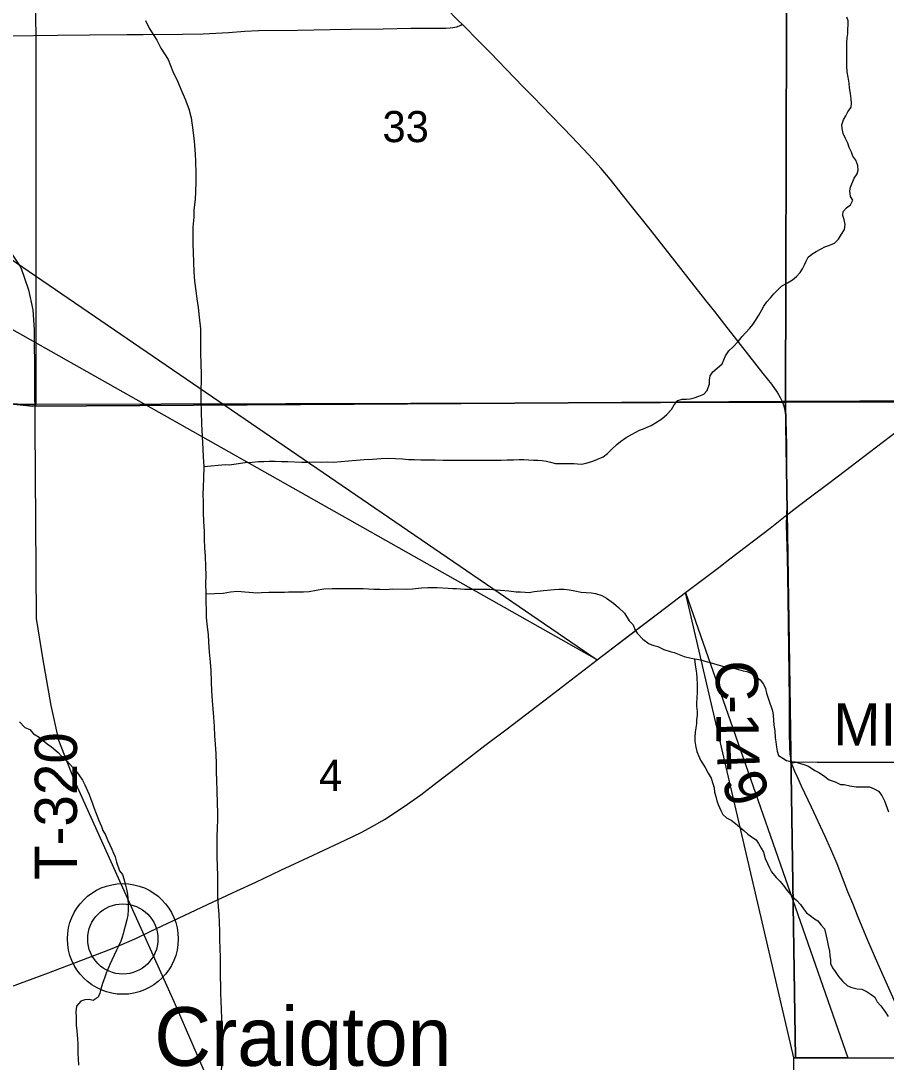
# Model space of a CAD drawing. Extents: x 0 to 34, y 0 to 22.
# Drawn here: x 5.452 to 6.615, y 17.529 to 18.929 of the extents above; entities that cross this region are included whole.
import ezdxf

# ---------------------------------------------------------------- set-up
doc = ezdxf.new("R2010")
doc.units = 0
for name, color, linetype in [('Default', 7, 'Continuous'), ('GM_X_County_Road', 7, 'Continuous'), ('GM_X_County_Road_Text', 7, 'Continuous'), ('GM_X_Minor_River', 7, 'Continuous'), ('GM_X_Rail_Line', 7, 'Continuous'), ('GM_X_Section', 7, 'Continuous'), ('GM_X_Section_Text', 7, 'Continuous'), ('GM_X_State_Route', 7, 'Continuous'), ('GM_X_Township_Road', 7, 'Continuous'), ('GM_X_Township_Road_Text', 7, 'Continuous'), ('GM_X_Unincorporated', 7, 'Continuous'), ('GM_X_Unincorporated_Location', 7, 'Continuous'), ('GM_X_Unincorporated_Text', 7, 'Continuous'), ('SH_Text', 7, 'Continuous')]:
    doc.layers.add(name, color=color, linetype=linetype)

msp = doc.modelspace()

# ---------------------------------------------------------------- linework, layer by layer
at = {"layer": 'Default'}
for points in [[(5.3223, 18.688), (6.2262, 18.0698), (5.3223, 18.5805)], [(6.4908, 17.5349), (6.3453, 18.1606), (6.5634, 17.5349)]]:
    msp.add_lwpolyline(points, close=True, dxfattribs=at)
for points in [[(6.6827, 18.4182), (6.4755, 18.4174), (5.4679, 18.4109), (5.4247, 18.4153)], [(5.4247, 18.4153), (5.4679, 18.4109), (6.4755, 18.4174), (6.6827, 18.4182)]]:
    msp.add_lwpolyline(points, dxfattribs=at)
at = {"layer": 'GM_X_County_Road'}
for points in [[(6.0449, 18.9245), (6.0402, 18.9292), (6.0056, 18.9649), (5.976, 18.9964)], [(6.4757, 18.4168), (6.473, 18.4223), (6.4682, 18.4302), (6.4612, 18.4404), (6.4497, 18.4551), (6.4189, 18.494), (6.3979, 18.5209), (6.3844, 18.5381), (6.3749, 18.5503), (6.3614, 18.5673), (6.3306, 18.6063), (6.2982, 18.6481), (6.2691, 18.6845), (6.2439, 18.716), (6.232, 18.7303), (6.2154, 18.7488), (6.1919, 18.7736), (6.1811, 18.7847), (6.1638, 18.8026), (6.1531, 18.8138), (6.14, 18.8271), (6.1269, 18.8403), (6.0928, 18.8755), (6.0838, 18.8849), (6.0686, 18.9005), (6.0449, 18.9245)], [(6.4811, 18.2648), (6.4816, 18.2769), (6.4816, 18.2879), (6.4814, 18.3003), (6.4813, 18.3314), (6.4811, 18.3562), (6.4807, 18.3774), (6.4805, 18.3899), (6.4801, 18.3991), (6.4792, 18.4051), (6.4778, 18.4111), (6.4757, 18.4168)], [(6.4879, 17.9317), (6.4874, 17.9337), (6.4865, 17.9376), (6.4858, 17.9431), (6.4853, 17.9528), (6.4849, 17.9715), (6.4847, 18.015), (6.4844, 18.0523), (6.4838, 18.0834), (6.4834, 18.1207), (6.4825, 18.1829), (6.4821, 18.2078), (6.4807, 18.2517), (6.4811, 18.2648)], [(6.4879, 17.9317), (6.4945, 17.9326), (6.5036, 17.9327), (6.5222, 17.9326), (6.544, 17.9325), (6.6029, 17.9324), (6.6277, 17.9324)], [(6.6597, 17.5349), (6.6531, 17.5517), (6.6469, 17.5659), (6.6353, 17.591), (6.6286, 17.6054), (6.6203, 17.6244), (6.6037, 17.6616), (6.5904, 17.6928), (6.5774, 17.7243), (6.5699, 17.7425), (6.5635, 17.7581), (6.5488, 17.7957), (6.5406, 17.8156), (6.533, 17.8326), (6.5144, 17.872), (6.5011, 17.9), (6.4959, 17.9113), (6.4922, 17.9198), (6.4891, 17.9279), (6.4879, 17.9317)]]:
    msp.add_lwpolyline(points, dxfattribs=at)
at = {"layer": 'GM_X_Minor_River'}
for points in [[(5.6195, 18.9296), (5.6245, 18.919), (5.6344, 18.9031), (5.6401, 18.8921), (5.6497, 18.877), (5.6562, 18.861), (5.6623, 18.8478), (5.6684, 18.8341), (5.6726, 18.8239), (5.6776, 18.8106), (5.6806, 18.7985), (5.683, 18.7822), (5.6846, 18.767)], [(6.4503, 18.5452), (6.4545, 18.5513), (6.4594, 18.5566), (6.464, 18.5619), (6.469, 18.5676), (6.4743, 18.5722), (6.4823, 18.5767), (6.4888, 18.5809), (6.4945, 18.5855), (6.4994, 18.5908), (6.5025, 18.5957), (6.5051, 18.6011), (6.5074, 18.606), (6.5101, 18.6113), (6.515, 18.6151), (6.5207, 18.6189), (6.5276, 18.6227), (6.5326, 18.6254), (6.5379, 18.6269), (6.5455, 18.6303), (6.5508, 18.6353), (6.555, 18.6421), (6.5588, 18.6486), (6.5596, 18.655), (6.5584, 18.6619), (6.5565, 18.6672), (6.5569, 18.6725), (6.5614, 18.6778), (6.5668, 18.6816), (6.5702, 18.6877), (6.5671, 18.6927), (6.566, 18.7003), (6.5671, 18.7056), (6.5716, 18.7174), (6.5758, 18.7231), (6.577, 18.7284), (6.5766, 18.7345), (6.5739, 18.7417), (6.57, 18.747), (6.5681, 18.7524), (6.5651, 18.7588), (6.5631, 18.7645), (6.5601, 18.771), (6.557, 18.7775), (6.5555, 18.7843), (6.5554, 18.7893), (6.5573, 18.7957), (6.5604, 18.8014), (6.5634, 18.8068), (6.5676, 18.8128), (6.5683, 18.8182), (6.568, 18.8242), (6.5668, 18.8315), (6.5656, 18.8391), (6.5652, 18.8452), (6.5637, 18.8531), (6.5625, 18.8604), (6.5621, 18.868), (6.5621, 18.8995), (6.5624, 18.906), (6.5632, 18.9117), (6.5635, 18.9174), (6.5639, 18.9239), (6.5639, 18.9288), (6.562, 18.9341)], [(5.6846, 18.767), (5.6861, 18.7499), (5.6866, 18.7401), (5.687, 18.7237), (5.687, 18.7131), (5.6867, 18.6991), (5.686, 18.6888), (5.6845, 18.6751), (5.6842, 18.6649), (5.6831, 18.6516), (5.6831, 18.6414), (5.6828, 18.6288), (5.6832, 18.6175), (5.6837, 18.6046), (5.6845, 18.5917), (5.6853, 18.5791), (5.6872, 18.5659), (5.6884, 18.5552), (5.6903, 18.5435), (5.6915, 18.5306), (5.6931, 18.515), (5.6932, 18.4839), (5.6937, 18.4661), (5.6941, 18.4558), (5.6941, 18.4456), (5.6938, 18.433), (5.6939, 18.4186), (5.6943, 18.4034), (5.6947, 18.3871), (5.6956, 18.37), (5.6964, 18.3533), (5.6968, 18.3427), (5.6976, 18.3294), (5.6973, 18.3146), (5.6969, 18.3021), (5.6966, 18.2926), (5.697, 18.282), (5.6967, 18.2687), (5.6975, 18.2554), (5.6983, 18.2433), (5.6984, 18.2323), (5.6988, 18.2205), (5.6996, 18.2095), (5.7, 18.1951), (5.7004, 18.1837), (5.7001, 18.1723), (5.7005, 18.1594), (5.7006, 18.1484), (5.701, 18.1366), (5.701, 18.1271), (5.7022, 18.1142), (5.7034, 18.104), (5.7042, 18.0938), (5.705, 18.0805), (5.7062, 18.0668), (5.707, 18.0558), (5.7074, 18.0403), (5.7082, 18.0285), (5.709, 18.0148), (5.7098, 18.0042), (5.7106, 17.9928), (5.7118, 17.9803), (5.7122, 17.9678), (5.713, 17.9568), (5.7139, 17.9435), (5.7143, 17.9298), (5.7143, 17.9196), (5.7147, 17.9074), (5.7152, 17.8938), (5.7156, 17.8775), (5.7161, 17.8642), (5.7161, 17.8547), (5.7157, 17.8448), (5.7154, 17.8315), (5.7151, 17.8194), (5.7151, 17.8061), (5.7156, 17.7924), (5.716, 17.7803), (5.7161, 17.7628), (5.7161, 17.7511), (5.7169, 17.7378), (5.7177, 17.7279), (5.7185, 17.7165), (5.7189, 17.7059), (5.719, 17.6934), (5.7194, 17.682), (5.7198, 17.6702), (5.7195, 17.6585), (5.7195, 17.6444), (5.72, 17.6315), (5.72, 17.6213), (5.7204, 17.6118), (5.7213, 17.5883), (5.7217, 17.5754), (5.7221, 17.5644), (5.7226, 17.5518), (5.7226, 17.5408), (5.7223, 17.5298), (5.7208, 17.5158)], [(5.6976, 18.3301), (5.7268, 18.3327), (5.7318, 18.3323), (5.7382, 18.3331), (5.7535, 18.3354), (5.7627, 18.3357), (5.7711, 18.3365), (5.7783, 18.3365), (5.7856, 18.3369), (5.7936, 18.3369), (5.802, 18.3365), (5.8108, 18.3365), (5.8291, 18.3357), (5.8382, 18.3357), (5.847, 18.3361), (5.8558, 18.3357), (5.8642, 18.3361), (5.8726, 18.3357), (5.8821, 18.3364), (5.892, 18.3376), (5.9024, 18.3383), (5.9134, 18.3394), (5.9245, 18.3398), (5.9359, 18.3406), (5.9455, 18.3413), (5.9554, 18.3406), (5.9646, 18.3402), (5.973, 18.3394), (5.981, 18.3394), (5.9894, 18.339), (6.0085, 18.339), (6.0195, 18.3386), (6.0424, 18.3386), (6.0535, 18.3382), (6.0638, 18.3382), (6.073, 18.3386), (6.0894, 18.3386), (6.0974, 18.3382), (6.1054, 18.3389), (6.1138, 18.3389), (6.1214, 18.3393), (6.1279, 18.3393), (6.134, 18.3389), (6.1409, 18.3385), (6.1466, 18.3382), (6.1527, 18.3378), (6.1581, 18.337), (6.1638, 18.3355), (6.1703, 18.334), (6.1878, 18.3339), (6.1951, 18.3339), (6.2001, 18.3336), (6.2054, 18.3332), (6.2115, 18.3343), (6.2207, 18.337), (6.226, 18.3392), (6.2344, 18.343), (6.2405, 18.3472), (6.2458, 18.3529), (6.2527, 18.3594), (6.2576, 18.3636), (6.2656, 18.3689), (6.2736, 18.3734), (6.2832, 18.3788), (6.2885, 18.3807), (6.2934, 18.3829), (6.2988, 18.3852), (6.3049, 18.3886), (6.3133, 18.3939), (6.3201, 18.3996), (6.3262, 18.4065), (6.33, 18.4126), (6.335, 18.4186), (6.3407, 18.4202), (6.3464, 18.4202), (6.3514, 18.4209), (6.3567, 18.4224), (6.3632, 18.4243), (6.3697, 18.427), (6.3742, 18.4319), (6.3773, 18.4411), (6.3776, 18.446), (6.3784, 18.4517), (6.3818, 18.457), (6.3879, 18.462), (6.3944, 18.468), (6.3989, 18.4787), (6.4035, 18.4852), (6.4092, 18.4909), (6.4161, 18.4981), (6.4214, 18.5045), (6.4263, 18.5099), (6.4317, 18.5159), (6.4355, 18.5209), (6.4393, 18.5262), (6.4438, 18.5334), (6.4473, 18.5395), (6.4503, 18.5452)], [(5.7005, 18.1587), (5.7238, 18.1597), (5.7337, 18.1612), (5.7432, 18.1623), (5.7528, 18.1612), (5.77, 18.16), (5.7753, 18.1604), (5.7852, 18.1608), (5.8062, 18.1608), (5.8116, 18.1612), (5.8318, 18.1612), (5.8394, 18.1619), (5.8486, 18.1638), (5.8589, 18.1653), (5.8703, 18.1657), (5.8822, 18.1661), (5.8928, 18.1657), (5.9119, 18.1657), (5.9264, 18.1649), (5.9341, 18.1649), (5.9425, 18.1645), (5.9512, 18.1653), (5.9696, 18.1652), (5.978, 18.1656), (5.9902, 18.1668), (5.9986, 18.1671), (6.0115, 18.1671), (6.026, 18.1664), (6.0325, 18.166), (6.0375, 18.166), (6.0482, 18.1652), (6.0715, 18.1652), (6.0821, 18.1648), (6.0905, 18.164), (6.0963, 18.1636), (6.1024, 18.1633), (6.1077, 18.1629), (6.1176, 18.1614), (6.1234, 18.1613), (6.1295, 18.161), (6.1348, 18.1606), (6.1417, 18.1617), (6.1543, 18.1632), (6.1684, 18.1647), (6.1749, 18.1651), (6.1818, 18.1651), (6.189, 18.1643), (6.1966, 18.1628), (6.205, 18.1609), (6.2115, 18.1605), (6.2188, 18.1601), (6.2241, 18.159), (6.2325, 18.1563), (6.239, 18.1529), (6.2482, 18.1464), (6.2551, 18.1403), (6.2631, 18.1327), (6.2693, 18.1225), (6.2746, 18.1171), (6.2769, 18.1107), (6.28, 18.1057), (6.288, 18.0977), (6.2964, 18.0916), (6.3025, 18.0894), (6.3079, 18.0878), (6.3159, 18.084), (6.3243, 18.0814), (6.33, 18.0798), (6.3434, 18.0745), (6.3526, 18.0722), (6.3575, 18.0715), (6.3659, 18.0699), (6.3709, 18.068), (6.3812, 18.0654), (6.3885, 18.0631), (6.3934, 18.0619), (6.3988, 18.0608), (6.4037, 18.06), (6.4102, 18.0589), (6.4225, 18.0551), (6.4274, 18.0543), (6.4332, 18.052), (6.4397, 18.0475), (6.4454, 18.0429), (6.45, 18.0372), (6.4527, 18.0315), (6.4538, 18.025), (6.4584, 18.0117), (6.4604, 18.0068), (6.4619, 18.0014), (6.4631, 17.9957), (6.4639, 17.9824), (6.465, 17.9744), (6.4658, 17.9653), (6.4666, 17.9596), (6.4674, 17.9524), (6.4681, 17.9474), (6.4701, 17.9413), (6.4758, 17.9379), (6.4808, 17.9345), (6.4872, 17.9333)], [(6.3572, 18.0715), (6.3583, 18.0635), (6.3591, 18.0574), (6.3599, 18.0521), (6.3603, 18.0464), (6.3607, 18.0365), (6.3607, 18.027), (6.3603, 18.0182), (6.36, 18.0125), (6.36, 18.0076), (6.3608, 18.0007), (6.3608, 17.9954), (6.36, 17.9893), (6.3597, 17.984), (6.3589, 17.9787), (6.3582, 17.9726), (6.3578, 17.9661), (6.3578, 17.9608), (6.359, 17.9528), (6.3605, 17.9467), (6.3624, 17.9414), (6.3651, 17.9353), (6.3682, 17.93), (6.3716, 17.9251), (6.3755, 17.9178), (6.3797, 17.911), (6.382, 17.9037), (6.3835, 17.898), (6.3843, 17.8923), (6.3858, 17.8863), (6.3874, 17.8806), (6.3889, 17.8756), (6.3928, 17.8676), (6.3954, 17.8619), (6.4004, 17.8577), (6.4065, 17.8543), (6.4123, 17.8501), (6.418, 17.8452), (6.4237, 17.8406), (6.4287, 17.8357), (6.4352, 17.8311), (6.4402, 17.828), (6.4432, 17.8231), (6.4467, 17.817), (6.4501, 17.8113), (6.4521, 17.8029), (6.4555, 17.7961), (6.4578, 17.7904), (6.4605, 17.7851), (6.467, 17.7775), (6.472, 17.7725), (6.477, 17.7668), (6.4812, 17.7603), (6.4888, 17.7516), (6.4946, 17.7466), (6.4995, 17.7413), (6.5037, 17.7352), (6.5076, 17.7299), (6.5125, 17.7265), (6.5183, 17.7219), (6.5232, 17.7192), (6.5275, 17.7135), (6.5321, 17.7082), (6.5336, 17.701), (6.5355, 17.6926), (6.5367, 17.6858), (6.5386, 17.6782), (6.539, 17.6721), (6.5398, 17.6671), (6.5402, 17.6618), (6.5429, 17.6561), (6.5463, 17.6512), (6.5509, 17.6443), (6.5566, 17.6375), (6.5628, 17.6318), (6.5685, 17.6295), (6.5757, 17.6279), (6.5822, 17.6272), (6.5895, 17.6238), (6.5945, 17.62), (6.5994, 17.6165), (6.6029, 17.6104), (6.6075, 17.6047), (6.6136, 17.5967), (6.6174, 17.5907)], [(5.4502, 17.9865), (5.4574, 17.9792), (5.4639, 17.9762), (5.4689, 17.9705), (5.4766, 17.9659), (5.4873, 17.9572), (5.493, 17.953), (5.5022, 17.9454), (5.5071, 17.94), (5.5133, 17.9347), (5.5263, 17.9203), (5.5297, 17.9153), (5.5347, 17.9081), (5.5378, 17.902), (5.5412, 17.894), (5.5435, 17.8891), (5.5458, 17.8826), (5.5481, 17.8769), (5.5501, 17.8716), (5.5531, 17.8636), (5.5566, 17.8541), (5.5604, 17.8461), (5.562, 17.8408), (5.5658, 17.8347), (5.5681, 17.8282), (5.5715, 17.8214), (5.5739, 17.8157), (5.5762, 17.8103), (5.5785, 17.8054), (5.5804, 17.7982), (5.5846, 17.7864), (5.5884, 17.7814)], [(6.4872, 17.9333), (6.4922, 17.933), (6.504, 17.9292), (6.5105, 17.9272), (6.519, 17.9212), (6.5243, 17.9185), (6.5304, 17.9143), (6.5384, 17.9086), (6.5461, 17.9059), (6.5533, 17.9025), (6.5583, 17.9025), (6.5659, 17.9006), (6.5747, 17.8991), (6.5804, 17.8991), (6.5854, 17.8994), (6.5923, 17.8991), (6.5988, 17.8964), (6.6045, 17.8934), (6.6091, 17.8876), (6.6126, 17.8804), (6.6179, 17.8656)], [(5.5884, 17.7814), (5.5904, 17.7757), (5.5927, 17.7673), (5.5938, 17.7616), (5.595, 17.7552), (5.5958, 17.7491), (5.5962, 17.7407), (5.5962, 17.7339), (5.5958, 17.7267), (5.5943, 17.7206), (5.592, 17.7122), (5.5905, 17.7073), (5.5894, 17.7019), (5.5879, 17.697), (5.586, 17.6917), (5.5837, 17.686), (5.5803, 17.6799), (5.5742, 17.6662), (5.5715, 17.6605), (5.5689, 17.6544), (5.5666, 17.6487), (5.5647, 17.6434), (5.5617, 17.635), (5.5594, 17.6274), (5.5579, 17.6221), (5.5556, 17.6164), (5.5491, 17.6122), (5.5438, 17.6134), (5.5377, 17.613), (5.5324, 17.6111), (5.5266, 17.6046), (5.5259, 17.597), (5.5263, 17.5902), (5.5263, 17.5788), (5.5271, 17.5712), (5.5275, 17.5658), (5.5279, 17.5601), (5.5283, 17.5537), (5.5283, 17.5404), (5.5287, 17.5343), (5.5291, 17.5252)]]:
    msp.add_lwpolyline(points, dxfattribs=at)
at = {"layer": 'GM_X_Rail_Line'}
msp.add_lwpolyline([(5.3223, 18.8195), (5.4276, 18.6336), (5.4516, 18.5976), (5.462, 18.5676), (5.468, 18.5406), (5.4695, 18.5137), (5.4725, 18.1255), (5.4814, 18.07), (5.4919, 18.0086), (5.5024, 17.9621), (5.5234, 17.9081), (5.6581, 17.6099), (5.724, 17.457), (5.7449, 17.406), (5.7674, 17.3506), (5.7973, 17.2561), (5.8333, 17.1242), (5.8662, 16.9938), (5.8901, 16.8859), (5.8901, 16.8575), (5.8886, 16.8335), (5.7201, 16.39)], dxfattribs=at)
at = {"layer": 'GM_X_Section'}
for points in [[(6.4824, 19.4291), (7.5091, 19.4296), (7.4947, 18.4172), (6.4793, 18.4161)], [(4.4724, 18.5805), (4.4738, 18.4018), (5.4223, 18.414), (5.4724, 18.4134), (5.472, 19.4291), (4.4662, 19.4189), (4.4671, 19.2976), (5.3223, 19.2976), (5.3223, 18.5805)], [(5.472, 19.4291), (6.4824, 19.4291), (6.4793, 18.4161), (5.4724, 18.4134)], [(6.4931, 17.5349), (6.4793, 18.4161), (5.4724, 18.4134), (5.4223, 18.414), (5.4312, 17.3835), (6.4908, 17.4246), (6.4908, 17.5349)], [(7.5121, 17.5349), (7.5102, 18.4173), (7.4947, 18.4172), (6.4793, 18.4161), (6.4931, 17.5349)]]:
    msp.add_lwpolyline(points, close=True, dxfattribs=at)
at = {"layer": 'GM_X_State_Route'}
msp.add_line((6.2262, 18.0698), (6.3453, 18.1606), dxfattribs=at)
for points in [[(6.4843, 18.2673), (6.4906, 18.2721), (6.5129, 18.289), (6.5378, 18.3076), (6.56, 18.3245), (6.5922, 18.349), (6.6489, 18.3923), (6.6613, 18.4016), (6.6763, 18.4127), (6.6829, 18.4176)], [(5.6255, 17.7046), (5.7029, 17.7409), (5.7423, 17.7593), (5.7676, 17.7712), (5.8013, 17.7873), (5.8379, 17.8042), (5.8801, 17.824), (5.8969, 17.8321), (5.9108, 17.8389), (5.9271, 17.8478), (5.9405, 17.8556), (5.9562, 17.8656), (5.9716, 17.876), (5.9892, 17.8887), (6.0115, 17.9056), (6.0436, 17.9301), (6.0756, 17.9548), (6.1053, 17.9773), (6.1622, 18.0205), (6.2262, 18.0698), (6.2857, 18.1151), (6.3206, 18.1418), (6.3453, 18.1606), (6.37, 18.1793), (6.3897, 18.1943), (6.4045, 18.2057), (6.4588, 18.2472), (6.4811, 18.2648), (6.4843, 18.2673)], [(5.2011, 17.5256), (5.2227, 17.5389), (5.2386, 17.5478), (5.2551, 17.5564), (5.2775, 17.5674), (5.2945, 17.5751), (5.3175, 17.5845), (5.3377, 17.5924), (5.3668, 17.6034), (5.4133, 17.6208), (5.4332, 17.6284), (5.4394, 17.6307), (5.4889, 17.6494), (5.5702, 17.6802), (5.5874, 17.6872), (5.6073, 17.696), (5.6255, 17.7046)]]:
    msp.add_lwpolyline(points, dxfattribs=at)
at = {"layer": 'GM_X_Township_Road'}
msp.add_lwpolyline([(5.4361, 18.909), (5.5013, 18.9098), (5.5447, 18.9101), (5.5944, 18.9105), (5.6163, 18.9106), (5.6689, 18.911), (5.697, 18.9115), (5.7308, 18.9135), (5.7527, 18.9151), (5.7714, 18.9159), (5.8242, 18.9166), (5.8676, 18.9173), (5.8956, 18.9177), (5.939, 18.9182), (5.9761, 18.9189), (6.0073, 18.9193), (6.0228, 18.9193), (6.029, 18.9197), (6.0323, 18.92), (6.035, 18.9206), (6.0376, 18.921), (6.0395, 18.9216), (6.0414, 18.9223), (6.0431, 18.9232), (6.0449, 18.9245)], dxfattribs=at)
at = {"layer": 'GM_X_Unincorporated'}
for radius in [0.0744, 0.0472]:
    msp.add_circle((5.5889, 17.6948), radius, dxfattribs=at)
at = {"layer": 'GM_X_Unincorporated_Location'}
msp.add_line((5.5889, 17.6948), (5.5889, 17.6948), dxfattribs=at)
at = {"layer": 'SH_Text'}
msp.add_lwpolyline([(6.4908, 17.5349), (8.7107, 17.5349), (8.7107, 16.8178), (6.4908, 16.8178)], close=True, dxfattribs=at)

# ---------------------------------------------------------------- texts
at = {"layer": 'GM_X_County_Road_Text'}
for s, height, rotation, p in [('C', 0.0568, 270.4391, (6.3858, 18.0691)), ('-', 0.0568, 270.4632, (6.3862, 18.0224)), ('MILLBROOK', 0.05682, 359.885, (6.5438, 17.9549)), ('1', 0.0568, 270.5792, (6.3864, 17.9989)), ('4', 0.0568, 272.1153, (6.3868, 17.9623)), ('9', 0.0568, 291.2073, (6.3922, 17.9071))]:
    msp.add_text(s, height=height, rotation=rotation, dxfattribs=at).set_placement(p)
at = {"layer": 'GM_X_Section_Text'}
for s, height, p in [('33', 0.04186, (5.9379, 18.7659)), ('4', 0.0419, (5.8525, 17.8937))]:
    msp.add_text(s, height=height, rotation=0, dxfattribs=at).set_placement(p)
at = {"layer": 'GM_X_Township_Road_Text'}
msp.add_text('T-320', height=0.05682, rotation=90, dxfattribs=at).set_placement((5.5273, 17.7742))
at = {"layer": 'GM_X_Unincorporated_Text'}
msp.add_text('Craigton', height=0.07898, rotation=0, dxfattribs=at).set_placement((5.6312, 17.5242))

doc.saveas('drawing.dxf')
